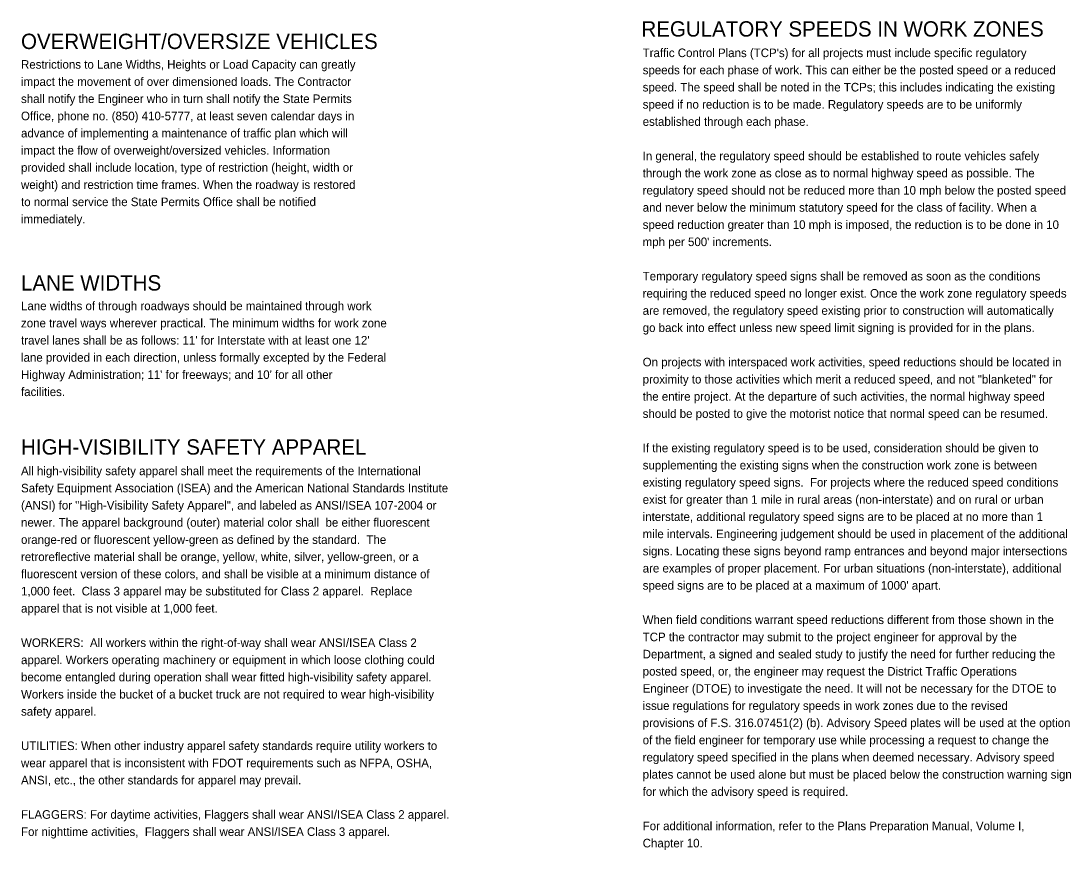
# Model space of a CAD drawing. Extents: x 9589 to 10706, y 9894 to 10509.
# Drawn here: x 10278.4 to 10706.3, y 10171.1 to 10508.9 of the extents above; entities that cross this region are included whole.
import ezdxf

# ---------------------------------------------------------------- set-up
doc = ezdxf.new("R2010")
doc.units = 0
doc.layers.add('PlotBorder_dp', color=7, linetype='Continuous')

msp = doc.modelspace()

# ---------------------------------------------------------------- texts
at = {"layer": 'PlotBorder_dp'}
for s, height, p in [('REGULATORY SPEEDS IN WORK ZONES', 6.25, (10531.22, 10502.51)), ('OVERWEIGHT/OVERSIZE VEHICLES', 6.25, (10278.4, 10497.44)), ("Traffic Control Plans (TCP's) for all projects must include specific regulatory ", 3.5, (10531.73, 10494.14)), ('speeds for each phase of work. This can either be the posted speed or a reduced ', 3.5, (10531.73, 10487.14)), ('speed. The speed shall be noted in the TCPs; this includes indicating the existing ', 3.5, (10531.73, 10480.14)), ('speed if no reduction is to be made. Regulatory speeds are to be uniformly ', 3.5, (10531.73, 10473.14)), ('established through each phase.', 3.5, (10531.73, 10466.14)), ('In general, the regulatory speed should be established to route vehicles safely ', 3.5, (10531.73, 10452.14)), ('through the work zone as close as to normal highway speed as possible. The ', 3.5, (10531.73, 10445.14)), ('regulatory speed should not be reduced more than 10 mph below the posted speed ', 3.5, (10531.73, 10438.14)), ('and never below the minimum statutory speed for the class of facility. When a ', 3.5, (10531.73, 10431.14)), ('speed reduction greater than 10 mph is imposed, the reduction is to be done in 10 ', 3.5, (10531.73, 10424.14)), ("mph per 500' increments.", 3.5, (10531.73, 10417.14)), ('Temporary regulatory speed signs shall be removed as soon as the conditions ', 3.5, (10531.73, 10403.14)), ('LANE WIDTHS', 6.25, (10278.4, 10399.04)), ('requiring the reduced speed no longer exist. Once the work zone regulatory speeds ', 3.5, (10531.73, 10396.14)), ('are removed, the regulatory speed existing prior to construction will automatically ', 3.5, (10531.73, 10389.14)), ('go back into effect unless new speed limit signing is provided for in the plans.', 3.5, (10531.73, 10382.14)), ('On projects with interspaced work activities, speed reductions should be located in ', 3.5, (10531.73, 10368.14)), ('proximity to those activities which merit a reduced speed, and not "blanketed" for ', 3.5, (10531.73, 10361.14)), ('the entire project. At the departure of such activities, the normal highway speed ', 3.5, (10531.73, 10354.14)), ('should be posted to give the motorist notice that normal speed can be resumed.', 3.5, (10531.73, 10347.14)), ('HIGH-VISIBILITY SAFETY APPAREL', 6.25, (10278.4, 10332.18)), ('If the existing regulatory speed is to be used, consideration should be given to ', 3.5, (10531.73, 10333.14)), ('supplementing the existing signs when the construction work zone is between ', 3.5, (10531.73, 10326.14)), ('All high-visibility safety apparel shall meet the requirements of the International ', 3.5, (10278.4, 10323.8)), ('Safety Equipment Association (ISEA) and the American National Standards Institute ', 3.5, (10278.4, 10316.8)), ('existing regulatory speed signs.  For projects where the reduced speed conditions ', 3.5, (10531.73, 10319.14)), ('(ANSI) for "High-Visibility Safety Apparel", and labeled as ANSI/ISEA 107-2004 or ', 3.5, (10278.4, 10309.8)), ('exist for greater than 1 mile in rural areas (non-interstate) and on rural or urban ', 3.5, (10531.73, 10312.14)), ('interstate, additional regulatory speed signs are to be placed at no more than 1 ', 3.5, (10531.73, 10305.14)), ('newer. The apparel background (outer) material color shall  be either fluorescent ', 3.5, (10278.4, 10302.8)), ('orange-red or fluorescent yellow-green as defined by the standard.  The ', 3.5, (10278.4, 10295.8)), ('mile intervals. Engineering judgement should be used in placement of the additional ', 3.5, (10531.73, 10298.14)), ('signs. Locating these signs beyond ramp entrances and beyond major intersections ', 3.5, (10531.73, 10291.14)), ('retroreflective material shall be orange, yellow, white, silver, yellow-green, or a ', 3.5, (10278.4, 10288.8)), ('are examples of proper placement. For urban situations (non-interstate), additional ', 3.5, (10531.73, 10284.14)), ('fluorescent version of these colors, and shall be visible at a minimum distance of ', 3.5, (10278.4, 10281.8)), ('1,000 feet.  Class 3 apparel may be substituted for Class 2 apparel.  Replace ', 3.5, (10278.4, 10274.8)), ("speed signs are to be placed at a maximum of 1000' apart.", 3.5, (10531.73, 10277.14)), ('apparel that is not visible at 1,000 feet.', 3.5, (10278.4, 10267.8)), ('When field conditions warrant speed reductions different from those shown in the ', 3.5, (10531.73, 10263.14)), ('WORKERS:  All workers within the right-of-way shall wear ANSI/ISEA Class 2 ', 3.5, (10278.4, 10253.8)), ('TCP the contractor may submit to the project engineer for approval by the ', 3.5, (10531.73, 10256.14)), ('Department, a signed and sealed study to justify the need for further reducing the ', 3.5, (10531.73, 10249.14)), ('apparel. Workers operating machinery or equipment in which loose clothing could ', 3.5, (10278.4, 10246.8)), ('become entangled during operation shall wear fitted high-visibility safety apparel. ', 3.5, (10278.4, 10239.8)), ('posted speed, or, the engineer may request the District Traffic Operations ', 3.5, (10531.73, 10242.14)), ('Workers inside the bucket of a bucket truck are not required to wear high-visibility ', 3.5, (10278.4, 10232.8)), ('Engineer (DTOE) to investigate the need. It will not be necessary for the DTOE to ', 3.5, (10531.73, 10235.14)), ('issue regulations for regulatory speeds in work zones due to the revised ', 3.5, (10531.73, 10228.14)), ('safety apparel.', 3.5, (10278.4, 10225.8)), ('provisions of F.S. 316.07451(2) (b). Advisory Speed plates will be used at the option ', 3.5, (10531.73, 10221.14)), ('of the field engineer for temporary use while processing a request to change the ', 3.5, (10531.73, 10214.14)), ('UTILITIES: When other industry apparel safety standards require utility workers to ', 3.5, (10278.4, 10211.8)), ('regulatory speed specified in the plans when deemed necessary. Advisory speed ', 3.5, (10531.73, 10207.14)), ('wear apparel that is inconsistent with FDOT requirements such as NFPA, OSHA, ', 3.5, (10278.4, 10204.8)), ('ANSI, etc., the other standards for apparel may prevail.  ', 3.5, (10278.4, 10197.8)), ('plates cannot be used alone but must be placed below the construction warning sign ', 3.5, (10531.73, 10200.14)), ('for which the advisory speed is required.', 3.5, (10531.73, 10193.14)), ('FLAGGERS: For daytime activities, Flaggers shall wear ANSI/ISEA Class 2 apparel. ', 3.5, (10278.4, 10183.8)), ('For nighttime activities,  Flaggers shall wear ANSI/ISEA Class 3 apparel.', 3.5, (10278.4, 10176.8)), ('For additional information, refer to the Plans Preparation Manual, Volume I, ', 3.5, (10531.73, 10179.14)), ('Chapter 10.', 3.5, (10531.73, 10172.14))]:
    msp.add_text(s, height=height, dxfattribs=at).set_placement(p)
for s, p in [('Restrictions to Lane Widths, Heights or Load Capacity can greatly ', (10278.4, 10489.42)), ('impact the movement of over dimensioned loads. The Contractor ', (10278.4, 10482.42)), ('shall notify the Engineer who in turn shall notify the State Permits ', (10278.4, 10475.42)), ('Office, phone no. (850) 410-5777, at least seven calendar days in ', (10278.4, 10468.42)), ('advance of implementing a maintenance of traffic plan which will ', (10278.4, 10461.42)), ('impact the flow of overweight/oversized vehicles. Information ', (10278.4, 10454.42)), ('provided shall include location, type of restriction (height, width or ', (10278.4, 10447.42)), ('weight) and restriction time frames. When the roadway is restored ', (10278.4, 10440.42)), ('to normal service the State Permits Office shall be notified ', (10278.4, 10433.42)), ('immediately. ', (10278.4, 10426.42)), ('Lane widths of through roadways should be maintained through work ', (10278.4, 10391.03)), ('zone travel ways wherever practical. The minimum widths for work zone ', (10278.4, 10384.03)), ("travel lanes shall be as follows: 11' for Interstate with at least one 12' ", (10278.4, 10377.03)), ('lane provided in each direction, unless formally excepted by the Federal  ', (10278.4, 10370.03)), ("Highway Administration; 11' for freeways; and 10' for all other ", (10278.4, 10363.03)), ('facilities. ', (10278.4, 10356.03))]:
    msp.add_text(s, height=3.5, rotation=359.9982, dxfattribs=at).set_placement(p)

doc.saveas('drawing.dxf')
